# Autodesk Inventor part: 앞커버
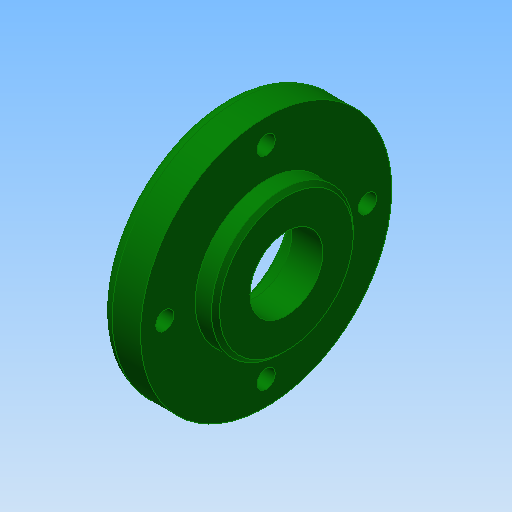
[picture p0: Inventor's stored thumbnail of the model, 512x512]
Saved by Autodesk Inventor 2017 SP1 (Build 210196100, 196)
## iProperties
Created: 2015-12
Part Number: 앞커버
Document SubType Name: Modeling
Designer: mdu
Density: 2.71 g/cm^3
Material: 알루미늄 6061
Appearance: 진녹색
Author: mdu
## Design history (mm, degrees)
sketch "스케치1"
  geometry: L1 (-7.5, 0)-(7.5, 0); L2 (-7.5, 0)-(-7.5, 31); L3 (-7.5, 31)-(2.5, 31); L4 (2.5, 31)-(2.5, 17.5); L5 (2.5, 17.5)-(7.5, 17.5); L6 (7.5, 17.5)-(7.5, 0); 2 further points
  constraints: 12 end point, 3 perpendicular, 1 coincident, 1 horizontal, 1 midpoint, 1 parallel
  dimensions: "d0" = 15 distance of L1.start L1.end; "d1" = 62 diameter of L3 L1; "d2" = 35 diameter of L5 L1; "d5" = 10 distance of L2.end L3.end
revolve "회전1" sketch "스케치1" stored, may be unused: angle "d6" = 90 deg
sketch "스케치2" dims "d42" = 50
  geometry: 3 further points
  constraints: 2 vertical alignment, 1 coincident, 2 other
hole "구멍1" sketch "스케치2" at (0, 25) diameter "d8" = 4.5; stored, may be unused: countersink angle "d12" = 90 deg, drill point angle "d14" = 118 deg; dims "d9" = 6, "d10" = 8, "d11" = 4.4, "d13" = 8
hole "구멍2" diameter "d20" = 18; stored, may be unused: countersink angle "d24" = 90 deg, drill point angle "d26" = 0 deg; dims "d18" = 10, "d19" = 10, "d21" = 6, "d22" = 8, "d23" = 4.4, "d25" = 8
hole "구멍3" diameter "d34" = 30; stored, may be unused: countersink angle "d38" = 90 deg, drill point angle "d40" = 0 deg; dims "d32" = 10, "d33" = 10, "d35" = 6, "d36" = 4, "d37" = 2, "d39" = 7.3
fillet "모깎기1" dims "d27" = 3, "d41" = 0.3
chamfer "모따기1" distance "d29" = 1; stored, may be unused: second distance "d30" = 2, angle "d31" = 45 deg
node "솔리드1"
pattern_circular "원형 패턴1" dims angle "d16" = 360 deg
